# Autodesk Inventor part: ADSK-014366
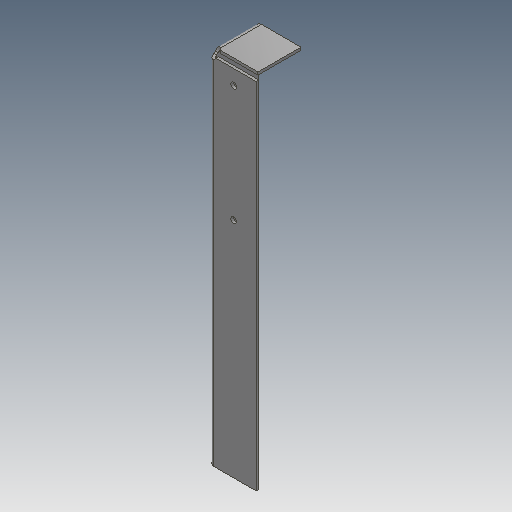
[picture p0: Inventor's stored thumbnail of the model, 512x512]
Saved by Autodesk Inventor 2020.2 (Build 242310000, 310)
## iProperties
Created: 2019-10
Part Number: ADSK-014366
Material: 1.0312 DC05
Document SubType Name: Blech
Designer: lutzd
Mass: 126.58 g
Surface Area: 878.095 cm^2
Volume: 126.58 cm^3
Density: 1 g/cm^3
Sheet Metal Rule: Stahlblech 1.0312 - DC05 -   3.0 mm
Appearance: Stahl
Flat Pattern Width: 44.4786 cm
Flat Pattern Length: 10.0786 cm
Flat Pattern Area: 448.281 cm^2
Sheet Metal Width: 444,786 mm
Sheet Metal Length: 100,786 mm
Sheet Metal Area: 44828,115 mm^2
VLDS_Profile: Default Part
VLDS_TimeStamp: 2016-07-29
VLDS_FailCnt: 0
VLDS_AcceptCnt: 0
Dimensions: 53,1x400,1x53,1 mm
Semi finished: Stahlblech 1.0312 - DC05 -   3.0 mm
Mass: 0,127 kg
DocNumber: ADSK-014366
Folder: 01 - Themengebiete\Simplification\01 - Packaging machine\Parts\
VDS_Category: 3D Komponenten
VDS_NumSchm: Autodesk
G_L: 444,8x100,8 mm
Thickness: 3,000 mm
VLT_Material: 1.0312 DC05
Title: rail
Author: lutzd
Revision Number: -
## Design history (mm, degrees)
node "Konturlasche1"
  sketch "Skizze1"
    geometry: L1 (0, 0)-(0, 50); L2 (0, 0)-(50, 0)
    constraints: 4 end point, 1 horizontal, 1 vertical
    dimensions: "d0" = 50 distance of L1.start L2.end; "d1" = 50 distance of L1.start L1.end
node "Direktbearbeitung1"
node "Lasche1"
feature "Ecke3" dims "d2" = 3 (= Stärke), "d35" = 12 (= GrößeEckenfreistellung), "d36" = 3 (= Übergangsradius), "d37" = 3 (= Abstandsgröße), "d38" = 0, "d39" = 10
sketch "Skizze2"
  geometry: L1 (0, 700)-(0, 0) reference; L2 (-25, 451.5)-(-25, 321.5); L3 (-47, 300)-(-3, 300) reference; 2 further points
  constraints: 2 end point, 1 vertical, 1 vertical alignment
  dimensions: "d40" = 151.5 distance from line of L3 L2.start; "d41" = 130 distance of L2.start L2.end; "d42" = 25 distance between parallel lines of L1 L2
hole "Bohrung1" sketch "Skizze2" diameter "d15" = 6.6; stored, may be unused: countersink angle "d19" = 90 deg, drill point angle "d21" = 118 deg; dims "d16" = 16, "d17" = 12.6, "d18" = 2, "d20" = 3 (= Stärke)
node "Volumenkörper1"
feature "Grobblech1" dims "d2" = 3 (= Stärke), "d3" = 3 (= BreiteBiegungsfreistellung), "d4" = 1.5 (= TiefeBiegungsfreistellung), "d5" = 6 (= MinimalRest), "d6" = 3 (= Übergangsradius), "d7" = 700, "d8" = 3 (= Biegeradius), "d9" = 3, "d10" = 12 (= GrößeEckenfreistellung), "d11" = 3 (= Abstandsgröße), "d12" = 3 (= JacobiRadiusGröße), "AbstandVerbindung" = 0.01
feature "Biegung1" dims "d2" = 3 (= Stärke), "d3" = 3 (= BreiteBiegungsfreistellung), "d4" = 1.5 (= TiefeBiegungsfreistellung), "d5" = 6 (= MinimalRest), "d6" = 3 (= Übergangsradius), "d8" = 3 (= Biegeradius), "d9" = 3, "AbstandVerbindung" = 0.01
feature "Ecke1" dims "d9" = 3, "d10" = 12 (= GrößeEckenfreistellung), "d11" = 3 (= Abstandsgröße), "d12" = 3 (= JacobiRadiusGröße)
sketch "Skizze3"
  geometry: L1 through (0, 23.5) direction (1.18e-17, -1); L2 through (25, 0) direction (1, -8.19e-34); L3 (50, 0)-(50, 47); L4 (50, 47)-(0, 47)
  constraints: 6 end point, 1 horizontal, 1 perpendicular, 1 vertical
feature "Grobblech2" dims "d2" = 3 (= Stärke), "d25" = 3 (= BreiteBiegungsfreistellung), "d26" = 1.5 (= TiefeBiegungsfreistellung), "d27" = 6 (= MinimalRest), "d28" = 3 (= Übergangsradius), "d29" = 50, "d30" = 90 deg, "d31" = 3 (= Biegeradius), "d32" = 12 (= GrößeEckenfreistellung), "d33" = 3 (= Abstandsgröße), "d34" = 3 (= JacobiRadiusGröße), "AbstandVerbindung" = 0.01
feature "Biegung2" dims "d2" = 3 (= Stärke), "d25" = 3 (= BreiteBiegungsfreistellung), "d26" = 1.5 (= TiefeBiegungsfreistellung), "d27" = 6 (= MinimalRest), "d28" = 3 (= Übergangsradius), "d29" = 50, "d30" = 90 deg, "d31" = 3 (= Biegeradius), "AbstandVerbindung" = 0.01
feature "Ecke2" dims "d29" = 50, "d30" = 90 deg, "d32" = 12 (= GrößeEckenfreistellung), "d33" = 3 (= Abstandsgröße), "d34" = 3 (= JacobiRadiusGröße)
feature "Definition1"
feature "Verschieben1" dims "d24" = -300
other parameters: "Stärke" = 3 (derived), "KFaktor" = 4.4, "Biegeradius" = 3 (= Stärke), "BreiteBiegungsfreistellung" = 3 (= Stärke), "TiefeBiegungsfreistellung" = 1.5 (= 0.5 x Stärke), "GrößeEckenfreistellung" = 12 (= 4 x Stärke), "MinimalRest" = 6 (= 2 x Stärke), "Übergangsradius" = 3 (= Biegeradius), "JacobiRadiusGröße" = 3 (= Biegeradius), "Abstandsgröße" = 3 (= Stärke), "d22" = 0, "d23" = 0, "Abstandsgröße" = 3, "Biegeradius" = 3, "BreiteBiegungsfreistellung" = 3, "GrößeEckenfreistellung" = 12, "JacobiRadiusGröße" = 3, "MinimalRest" = 6, "Stärke" = 3, "TiefeBiegungsfreistellung" = 1.5, "Übergangsradius" = 3
